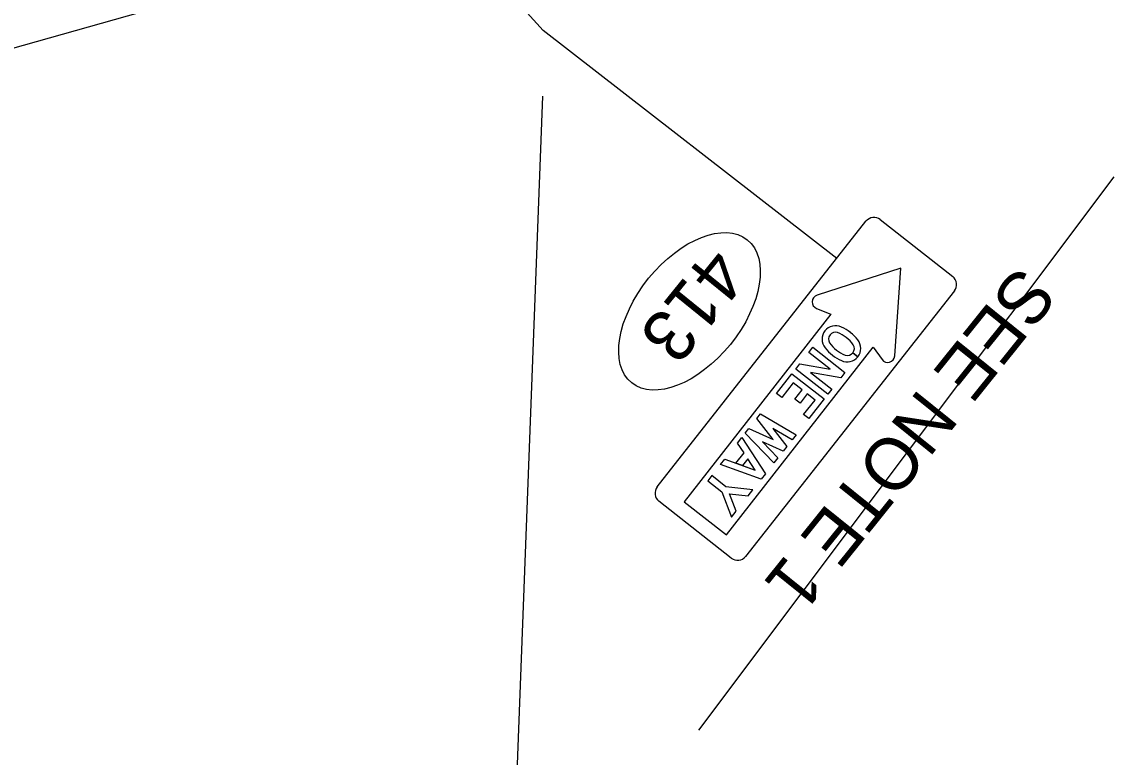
# Model space of a CAD drawing. Extents: x 2096670 to 2098561, y 684033 to 689893.
# Drawn here: x 2097700.1 to 2097952.2, y 687850.4 to 688020.1 of the extents above; entities that cross this region are included whole.
import ezdxf

# ---------------------------------------------------------------- set-up
doc = ezdxf.new("R2010")
doc.units = 0
for name, color, linetype in [('Prop DSN Text', 7, 'Continuous'), ('Prop Sign E One Way_Right CELL', 7, 'Continuous'), ('Scratch_Level_3', 7, 'Continuous'), ('Scratch_Level_4', 7, 'Continuous')]:
    doc.layers.add(name, color=color, linetype=linetype)

msp = doc.modelspace()

# ---------------------------------------------------------------- linework, layer by layer
at = {"layer": 'Prop DSN Text'}
msp.add_line((2097814.48, 688024.58), (2097820.46, 688018.05), dxfattribs=at)
at = {"layer": 'Prop Sign E One Way_Right CELL'}
for p, q in [((2097573.16, 687978.74), (2097759.04, 688031.27)), ((2097888.21, 687965.47), (2097820.46, 688018.05)), ((2097898.26, 687974.43), (2097914.98, 687961.29)), ((2097846.75, 687912.76), (2097894.95, 687974.04)), ((2097915.37, 687957.97), (2097867.17, 687896.7)), ((2097883.65, 687956.99), (2097883.65, 687956.99)), ((2097891.91, 687943.7), (2097893.1, 687942.76)), ((2097893.1, 687942.76), (2097891.91, 687943.7)), ((2097891.91, 687943.7), (2097891.91, 687943.7)), ((2097891.91, 687943.7), (2097893.1, 687942.76)), ((2097893.1, 687942.76), (2097891.91, 687943.7)), ((2097891.91, 687943.7), (2097891.91, 687943.7)), ((2097863.85, 687896.3), (2097847.14, 687909.45))]:
    msp.add_line(p, q, dxfattribs=at)
for points in [[(2097901.59, 687942.97), (2097902.97, 687963.22), (2097883.65, 687956.99)], [(2097901.59, 687942.97), (2097902.97, 687963.22), (2097883.65, 687956.99)], [(2097883.54, 687953.94), (2097886.81, 687952.61), (2097852.99, 687909.33), (2097862.76, 687901.69), (2097896.58, 687944.97), (2097898.66, 687942.12)]]:
    msp.add_lwpolyline(points, dxfattribs=at)
for points in [[(2097882.67, 687944.97), (2097890.1, 687939.13), (2097889.16, 687937.95), (2097882.13, 687939.18), (2097887.07, 687935.29), (2097886.15, 687934.12), (2097878.73, 687939.96), (2097879.65, 687941.13), (2097886.72, 687939.89), (2097881.75, 687943.8)], [(2097882.67, 687944.97), (2097890.1, 687939.13), (2097889.16, 687937.95), (2097882.13, 687939.18), (2097887.07, 687935.29), (2097886.15, 687934.12), (2097878.73, 687939.96), (2097879.65, 687941.13), (2097886.72, 687939.89), (2097881.75, 687943.8)], [(2097882.67, 687944.97), (2097890.1, 687939.13), (2097889.16, 687937.95), (2097882.13, 687939.18), (2097887.07, 687935.29), (2097886.15, 687934.12), (2097878.73, 687939.96), (2097879.65, 687941.13), (2097886.72, 687939.89), (2097881.75, 687943.8)], [(2097880.55, 687929.43), (2097883.19, 687932.8), (2097881.41, 687934.2), (2097879.74, 687932.08), (2097878.55, 687933.01), (2097880.22, 687935.14), (2097878.14, 687936.77), (2097875.49, 687933.41), (2097874.31, 687934.34), (2097877.87, 687938.88), (2097885.3, 687933.04), (2097881.73, 687928.5)], [(2097880.55, 687929.43), (2097883.19, 687932.8), (2097881.41, 687934.2), (2097879.74, 687932.08), (2097878.55, 687933.01), (2097880.22, 687935.14), (2097878.14, 687936.77), (2097875.49, 687933.41), (2097874.31, 687934.34), (2097877.87, 687938.88), (2097885.3, 687933.04), (2097881.73, 687928.5)], [(2097880.55, 687929.43), (2097883.19, 687932.8), (2097881.41, 687934.2), (2097879.74, 687932.08), (2097878.55, 687933.01), (2097880.22, 687935.14), (2097878.14, 687936.77), (2097875.49, 687933.41), (2097874.31, 687934.34), (2097877.87, 687938.88), (2097885.3, 687933.04), (2097881.73, 687928.5)], [(2097873.43, 687926.21), (2097876.68, 687922.08), (2097875.82, 687920.98), (2097871.04, 687923.17), (2097874.62, 687919.46), (2097873.69, 687918.28), (2097867.07, 687925.14), (2097867.93, 687926.24), (2097873.54, 687923.67), (2097869.72, 687928.51), (2097870.58, 687929.6), (2097878.81, 687924.79), (2097877.88, 687923.61)], [(2097873.43, 687926.21), (2097876.68, 687922.08), (2097875.82, 687920.98), (2097871.04, 687923.17), (2097874.62, 687919.46), (2097873.69, 687918.28), (2097867.07, 687925.14), (2097867.93, 687926.24), (2097873.54, 687923.67), (2097869.72, 687928.51), (2097870.58, 687929.6), (2097878.81, 687924.79), (2097877.88, 687923.61)], [(2097873.43, 687926.21), (2097876.68, 687922.08), (2097875.82, 687920.98), (2097871.04, 687923.17), (2097874.62, 687919.46), (2097873.69, 687918.28), (2097867.07, 687925.14), (2097867.93, 687926.24), (2097873.54, 687923.67), (2097869.72, 687928.51), (2097870.58, 687929.6), (2097878.81, 687924.79), (2097877.88, 687923.61)], [(2097866.8, 687920.59), (2097865.29, 687922.88), (2097866.27, 687924.12), (2097871.74, 687915.79), (2097870.76, 687914.55), (2097861.38, 687917.9), (2097862.35, 687919.14), (2097864.93, 687918.22)], [(2097866.27, 687924.12), (2097871.74, 687915.79), (2097870.76, 687914.55), (2097861.38, 687917.9), (2097862.35, 687919.14), (2097869.41, 687916.61), (2097867.67, 687919.26), (2097866.43, 687917.68), (2097864.93, 687918.22), (2097866.8, 687920.59), (2097865.29, 687922.88)], [(2097866.27, 687924.12), (2097871.74, 687915.79), (2097870.76, 687914.55), (2097861.38, 687917.9), (2097862.35, 687919.14), (2097869.41, 687916.61), (2097867.67, 687919.26), (2097866.43, 687917.68), (2097864.93, 687918.22), (2097866.8, 687920.59), (2097865.29, 687922.88)], [(2097867.67, 687919.26), (2097866.43, 687917.68), (2097869.41, 687916.61)], [(2097868.8, 687912.06), (2097862.62, 687912.8), (2097859.37, 687915.36), (2097858.45, 687914.19), (2097861.7, 687911.63), (2097863.88, 687905.8), (2097864.96, 687907.18), (2097863.46, 687911.19), (2097867.72, 687910.68)], [(2097868.8, 687912.06), (2097862.62, 687912.8), (2097859.37, 687915.36), (2097858.45, 687914.19), (2097861.7, 687911.63), (2097863.88, 687905.8), (2097864.96, 687907.18), (2097863.46, 687911.19), (2097867.72, 687910.68)], [(2097868.8, 687912.06), (2097862.62, 687912.8), (2097859.37, 687915.36), (2097858.45, 687914.19), (2097861.7, 687911.63), (2097863.88, 687905.8), (2097864.96, 687907.18), (2097863.46, 687911.19), (2097867.72, 687910.68)]]:
    msp.add_lwpolyline(points, close=True, dxfattribs=at)
for centre, radius, start, end in [((2097896.8, 687972.58), 2.36, 51.8113, 141.8105), ((2097913.51, 687959.43), 2.36, 321.8105, 51.8113), ((2097884.15, 687955.44), 1.62, 107.8795, 247.9515), ((2097899.97, 687943.08), 1.62, 216.0418, 356.1138), ((2097899.97, 687943.08), 1.62, 216.0418, 356.1138), ((2097848.6, 687911.3), 2.36, 141.8105, 231.8113), ((2097865.31, 687898.16), 2.36, 231.8113, 321.8105)]:
    msp.add_arc(centre, radius, start, end, dxfattribs=at)
msp.add_ellipse((2097854.21, 687953.26), major_axis=(13.35, 16.5), ratio=0.571429, dxfattribs=at)
for centre, major_axis, start_param, end_param in [((2097887.96, 687946.78), (2.51, -1.98), 1.799323, 3.134585), ((2097887.96, 687946.78), (2.51, -1.98), 1.799323, 3.134585), ((2097887.96, 687946.78), (2.51, -1.98), 1.799323, 3.134585), ((2097885.4, 687940.9), (7.62, -6), 1.565772, 1.814121), ((2097885.4, 687940.9), (7.62, -6), 1.565772, 1.814121), ((2097885.4, 687940.9), (7.62, -6), 1.565772, 1.814121), ((2097887.99, 687946.81), (2.51, -1.98), 3.1486, 4.483863), ((2097887.99, 687946.81), (2.51, -1.98), 3.1486, 4.483863), ((2097887.99, 687946.81), (2.51, -1.98), 3.1486, 4.483863), ((2097887.87, 687946.82), (1.24, -0.98), 3.110746, 4.362774), ((2097887.87, 687946.82), (1.24, -0.98), 3.110746, 4.362775), ((2097887.87, 687946.82), (1.24, -0.98), 3.110746, 4.362775), ((2097887.93, 687946.89), (1.24, -0.98), 1.920411, 3.172439), ((2097887.93, 687946.89), (1.24, -0.98), 1.920411, 3.172439), ((2097887.93, 687946.89), (1.24, -0.98), 1.920411, 3.172439), ((2097885.95, 687941.8), (5.59, -4.4), 1.546668, 1.87455), ((2097885.95, 687941.8), (5.59, -4.4), 1.546668, 1.87455), ((2097885.95, 687941.8), (5.59, -4.4), 1.546668, 1.87455), ((2097886.22, 687941.59), (5.59, -4.4), 1.267043, 1.594924), ((2097886.22, 687941.59), (5.59, -4.4), 1.267042, 1.594924), ((2097886.22, 687941.59), (5.59, -4.4), 1.267042, 1.594924), ((2097885.47, 687940.84), (7.62, -6), 1.327472, 1.575821), ((2097885.47, 687940.84), (7.62, -6), 1.327472, 1.575821), ((2097885.47, 687940.84), (7.62, -6), 1.327472, 1.575821), ((2097890.58, 687944.72), (2.51, -1.98), 0.007008, 1.34227), ((2097890.58, 687944.72), (2.51, -1.98), 0.007008, 1.34227), ((2097890.58, 687944.72), (2.51, -1.98), 0.007008, 1.34227), ((2097893.09, 687950.69), (7.62, -6), 4.469065, 4.717414), ((2097893.09, 687950.69), (7.62, -6), 4.469065, 4.717414), ((2097893.09, 687950.69), (7.62, -6), 4.469065, 4.717414), ((2097892.35, 687949.94), (5.59, -4.4), 4.408635, 4.736517), ((2097892.35, 687949.94), (5.59, -4.4), 4.408635, 4.736517), ((2097892.35, 687949.94), (5.59, -4.4), 4.408635, 4.736517), ((2097892.62, 687949.73), (5.59, -4.4), 4.688261, 5.016143), ((2097892.62, 687949.73), (5.59, -4.4), 4.688261, 5.016143), ((2097892.62, 687949.73), (5.59, -4.4), 4.688261, 5.016143), ((2097890.7, 687944.72), (1.24, -0.98), 6.252339, 7.504367), ((2097890.7, 687944.72), (1.24, -0.98), 6.252339, 7.504367), ((2097890.7, 687944.72), (1.24, -0.98), 6.252339, 7.504367), ((2097893.17, 687950.63), (7.62, -6), 4.707364, 4.955713), ((2097893.17, 687950.63), (7.62, -6), 4.707364, 4.955713), ((2097893.17, 687950.63), (7.62, -6), 4.707364, 4.955713), ((2097890.6, 687944.76), (2.51, -1.98), 4.940915, 6.276178), ((2097890.6, 687944.76), (2.51, -1.98), 4.940915, 6.27603), ((2097890.6, 687944.76), (2.51, -1.98), 4.940915, 6.27603), ((2097890.64, 687944.64), (1.24, -0.98), 5.062003, 6.314032), ((2097890.64, 687944.64), (1.24, -0.98), 5.062003, 6.313732), ((2097890.64, 687944.64), (1.24, -0.98), 5.062003, 6.313732)]:
    msp.add_ellipse(centre, major_axis=major_axis, ratio=0.985, start_param=start_param, end_param=end_param, dxfattribs=at)
at = {"layer": 'Scratch_Level_3'}
msp.add_line((2097856.36, 687856.6), (2097952.25, 687984.29), dxfattribs=at)
at = {"layer": 'Scratch_Level_4'}
msp.add_line((2097781.83, 686997.58), (2097820.39, 688002.92), dxfattribs=at)

# ---------------------------------------------------------------- texts
at = {"layer": 'Prop DSN Text'}
msp.add_text('SEE NOTE 1', height=12, rotation=231.2231, dxfattribs=at).set_placement((2097930.26, 687964.29))
at = {"layer": 'Prop Sign E One Way_Right CELL'}
msp.add_text('413', height=11.98, rotation=231.0201, dxfattribs=at).set_placement((2097859, 687968.7))

doc.saveas('drawing.dxf')
